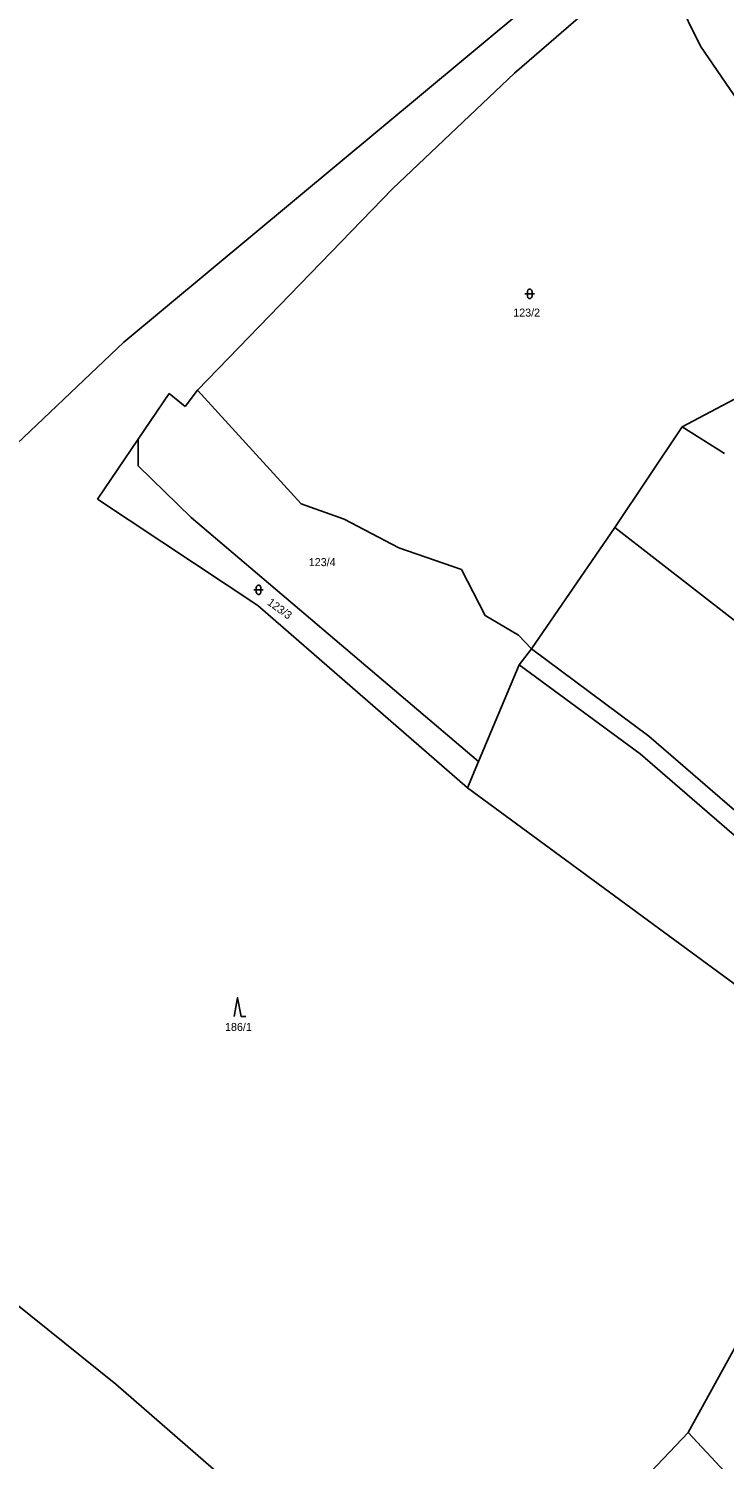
# Model space of a CAD drawing. Extents: x -811039 to -805820, y -1161436 to -1155864.
# Drawn here: x -807214.6 to -807066.9, y -1158370.8 to -1158066.9 of the extents above; entities that cross this region are included whole.
import ezdxf

# ---------------------------------------------------------------- set-up
doc = ezdxf.new("R2010")
doc.units = 0
for name, color, linetype in [('Default', 7, 'Continuous'), ('Hranice kat_území', 7, 'Continuous'), ('Hranice parcel', 7, 'Continuous'), ('Parcelní čísla', 7, 'Continuous'), ('Značky kultur', 7, 'Continuous')]:
    doc.layers.add(name, color=color, linetype=linetype)

# ---------------------------------------------------------------- blocks, each defined once
blk = doc.blocks.new('308')
at = {"layer": 'Default'}
blk.add_lwpolyline([(-0.75, 0), (0, 4), (0.75, 0), (1.75, 0)], dxfattribs=at)
blk = doc.blocks.new('316')
at = {"layer": 'Default'}
for points in [[(-1, 1), (0.27, 1), (1, 1)], [(-0.5, 1.5), (-0.4, 1.79), (-0.15, 1.97), (0.16, 1.97), (0.41, 1.79), (0.51, 1.5), (0.51, 0.5), (0.41, 0.21), (0.16, 0.03), (-0.15, 0.03), (-0.4, 0.21), (-0.5, 0.5), (-0.5, 1.5)]]:
    blk.add_lwpolyline(points, dxfattribs=at)

msp = doc.modelspace()

# ---------------------------------------------------------------- linework, layer by layer
at = {"layer": 'Hranice kat_území'}
for p, q in [((-807070.96, -1158030.65), (-807121.92, -1158073.2)), ((-807070.96, -1158030.65), (-807121.92, -1158073.2)), ((-807121.92, -1158073.2), (-807194.38, -1158133.53)), ((-807121.92, -1158073.2), (-807194.38, -1158133.53)), ((-807194.38, -1158133.53), (-807229.15, -1158166.58)), ((-807194.38, -1158133.53), (-807229.15, -1158166.58)), ((-807231.93, -1158325.98), (-807196.06, -1158354.81)), ((-807196.06, -1158354.81), (-807123.37, -1158417.96))]:
    msp.add_line(p, q, dxfattribs=at)
at = {"layer": 'Hranice parcel'}
for p, q in [((-807111.46, -1158076.42), (-807088.85, -1158056.84)), ((-807071.97, -1158070.67), (-807077.81, -1158058.66)), ((-807063.97, -1158082.38), (-807071.97, -1158070.67)), ((-807137.33, -1158100.94), (-807111.46, -1158076.42)), ((-807178.71, -1158143.71), (-807137.33, -1158100.94)), ((-807075.81, -1158151.48), (-807046.19, -1158135.84)), ((-807191.29, -1158154.12), (-807184.72, -1158144.46)), ((-807184.72, -1158144.46), (-807181.31, -1158147.22)), ((-807178.71, -1158143.71), (-807181.31, -1158147.22)), ((-807156.71, -1158167.86), (-807178.71, -1158143.71)), ((-807090.13, -1158172.9), (-807075.81, -1158151.48)), ((-807075.81, -1158151.48), (-807066.83, -1158157.18)), ((-807199.96, -1158166.86), (-807191.29, -1158154.12)), ((-807191.34, -1158159.77), (-807191.29, -1158154.12)), ((-807180.07, -1158170.75), (-807191.34, -1158159.77)), ((-807165.91, -1158189.47), (-807199.96, -1158166.86)), ((-807119.09, -1158222.61), (-807180.07, -1158170.75)), ((-807147.59, -1158171.14), (-807156.71, -1158167.86)), ((-807135.98, -1158177.21), (-807147.59, -1158171.14)), ((-807107.82, -1158198.66), (-807090.13, -1158172.9)), ((-807064.42, -1158192.88), (-807090.13, -1158172.9)), ((-807122.66, -1158181.8), (-807135.98, -1158177.21)), ((-807117.62, -1158191.59), (-807122.66, -1158181.8)), ((-807121.43, -1158228.14), (-807165.91, -1158189.47)), ((-807110.58, -1158195.76), (-807117.62, -1158191.59)), ((-807110.58, -1158195.76), (-807107.82, -1158198.66)), ((-807110.41, -1158202.06), (-807107.82, -1158198.66)), ((-807082.9, -1158217.2), (-807107.82, -1158198.66)), ((-807119.09, -1158222.61), (-807110.41, -1158202.06)), ((-807110.41, -1158202.06), (-807084.77, -1158220.97)), ((-807058.3, -1158238.51), (-807082.9, -1158217.2)), ((-807084.77, -1158220.97), (-807058.55, -1158243.68)), ((-807121.43, -1158228.14), (-807119.09, -1158222.61)), ((-807042.66, -1158286.07), (-807121.43, -1158228.14)), ((-807074.55, -1158365.1), (-807062.66, -1158343.51)), ((-807074.55, -1158365.1), (-807090.87, -1158382.23)), ((-807074.55, -1158365.1), (-807052.44, -1158388.69))]:
    msp.add_line(p, q, dxfattribs=at)

# ---------------------------------------------------------------- block references
at = {"layer": 'Značky kultur'}
for name, p in [('316', (-807108.2, -1158124.26)), ('316', (-807165.75, -1158187.12)), ('308', (-807170.19, -1158276.75))]:
    msp.add_blockref(name, p, dxfattribs=at)

# ---------------------------------------------------------------- texts
at = {"layer": 'Parcelní čísla'}
for s, p in [('123/2', (-807111.69, -1158128.1)), ('123/4', (-807155.09, -1158181.09)), ('186/1', (-807172.87, -1158279.8))]:
    msp.add_text(s, height=1.7, dxfattribs=at).set_placement(p)
msp.add_text('123/3', height=1.7, rotation=324.008, dxfattribs=at).set_placement((-807164.05, -1158189.14))

doc.saveas('drawing.dxf')
